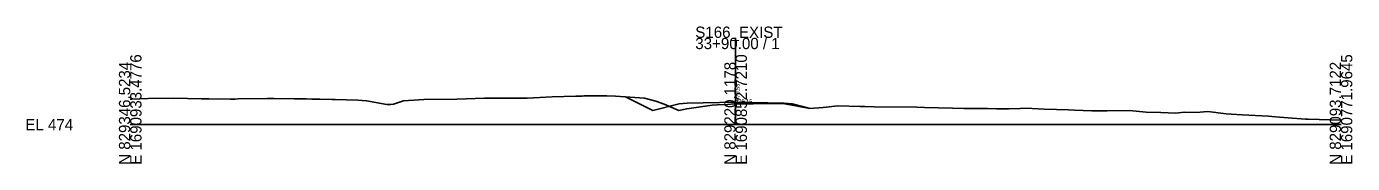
# Model space of a CAD drawing. Extents: x 1621104 to 1621433, y 1192880 to 1199414.
# Drawn here: x 1621104.2 to 1621432.7, y 1199379.5 to 1199413.7 of the extents above; entities that cross this region are included whole.
import ezdxf

# ---------------------------------------------------------------- set-up
doc = ezdxf.new("R2010")
doc.units = 0
for name, color, linetype in [('RD_GPK_XS_Cell', 7, 'Continuous'), ('RD_XS_EarthShd', 7, 'Continuous'), ('RD_XS_ExGround', 7, 'Continuous'), ('RD_XS_Pave', 7, 'Continuous'), ('RD_XS_TieSlope', 7, 'Continuous'), ('RD_XS_TX_Elev_EX', 7, 'Continuous'), ('RD_XS_TX_Elev_PR', 7, 'Continuous')]:
    doc.layers.add(name, color=color, linetype=linetype)

msp = doc.modelspace()

# ---------------------------------------------------------------- linework, layer by layer
at = {"layer": 'RD_GPK_XS_Cell'}
for p, q in [((1621279.86, 1199389.24), (1621279.86, 1199410.81)), ((1621129.86, 1199389.24), (1621279.86, 1199389.24)), ((1621279.86, 1199389.24), (1621429.86, 1199389.24))]:
    msp.add_line(p, q, dxfattribs=at)
at = {"layer": 'RD_XS_EarthShd'}
for p, q in [((1621267.86, 1199394.55), (1621265.86, 1199394.39)), ((1621291.86, 1199394.55), (1621293.86, 1199394.39))]:
    msp.add_line(p, q, dxfattribs=at)
at = {"layer": 'RD_XS_ExGround'}
msp.add_lwpolyline([(1621129.86, 1199395.56), (1621130.29, 1199395.6), (1621134.27, 1199395.7), (1621140.6, 1199395.83), (1621147.55, 1199395.66), (1621149.37, 1199395.64), (1621154.65, 1199395.53), (1621155.83, 1199395.6), (1621156.59, 1199395.64), (1621163.81, 1199395.69), (1621165.11, 1199395.71), (1621165.43, 1199395.7), (1621170.58, 1199395.64), (1621173.45, 1199395.61), (1621174.82, 1199395.55), (1621176.88, 1199395.56), (1621179.82, 1199395.48), (1621180.64, 1199395.45), (1621186.24, 1199395.33), (1621188.43, 1199395.16), (1621193.46, 1199394.21), (1621194.42, 1199394.22), (1621195.1, 1199394.36), (1621197.53, 1199395.13), (1621202.61, 1199395.48), (1621210.81, 1199395.59), (1621217.63, 1199395.79), (1621220.25, 1199395.83), (1621220.76, 1199395.84), (1621222.4, 1199395.83), (1621226.36, 1199395.84), (1621228.18, 1199395.84), (1621234.37, 1199396.16), (1621240.25, 1199396.27), (1621241.83, 1199396.35), (1621242.22, 1199396.36), (1621244.77, 1199396.38), (1621247.94, 1199396.43), (1621250.13, 1199396.34), (1621257.28, 1199395.85), (1621260.08, 1199395.07), (1621262.14, 1199394.29), (1621265.75, 1199392.77), (1621267.73, 1199393.19), (1621274.08, 1199394.1), (1621275.41, 1199394.15), (1621277.84, 1199394.27), (1621279.39, 1199394.39), (1621279.86, 1199394.39), (1621282.31, 1199394.41), (1621284.22, 1199394.37), (1621289.57, 1199394.46), (1621291.53, 1199394.46), (1621294.8, 1199393.92), (1621295.53, 1199393.72), (1621298.23, 1199393.26), (1621301.59, 1199393.47), (1621305.19, 1199393.87), (1621310.68, 1199393.72), (1621311.89, 1199393.7), (1621314.19, 1199393.65), (1621324.75, 1199393.54), (1621326.66, 1199393.52), (1621333.59, 1199393.32), (1621336.37, 1199393.25), (1621342.23, 1199393.26), (1621344.49, 1199393.15), (1621347.52, 1199393.16), (1621350.4, 1199393.28), (1621351.78, 1199393.36), (1621356.38, 1199393.1), (1621362.3, 1199392.89), (1621363.86, 1199392.82), (1621368.15, 1199392.7), (1621371.92, 1199392.67), (1621377.47, 1199392.76), (1621381.56, 1199392.35), (1621385.21, 1199392.26), (1621388.82, 1199392.12), (1621391.1, 1199392.34), (1621393.98, 1199392.23), (1621396.87, 1199392.48), (1621401.36, 1199391.94), (1621402.67, 1199391.82), (1621405.4, 1199391.67), (1621411.92, 1199391.33), (1621412.71, 1199391.24), (1621414.64, 1199391.11), (1621421.02, 1199390.61), (1621421.71, 1199390.55), (1621429.86, 1199390.3)], dxfattribs=at)
at = {"layer": 'RD_XS_Pave'}
for p, q in [((1621267.86, 1199394.55), (1621279.86, 1199394.79)), ((1621279.86, 1199394.79), (1621291.86, 1199394.55))]:
    msp.add_line(p, q, dxfattribs=at)
at = {"layer": 'RD_XS_TieSlope'}
for p, q in [((1621259.37, 1199392.77), (1621252.57, 1199396.17)), ((1621265.86, 1199394.39), (1621259.37, 1199392.77)), ((1621293.86, 1199394.39), (1621298.33, 1199393.27))]:
    msp.add_line(p, q, dxfattribs=at)

# ---------------------------------------------------------------- texts
at = {"layer": 'RD_GPK_XS_Cell'}
for s, p in [('S166_EXIST', (1621269.86, 1199410.81)), ('33+90.00 / 1', (1621269.86, 1199408.01)), ('EL 474', (1621103.86, 1199387.84))]:
    msp.add_text(s, height=2.8, dxfattribs=at).set_placement(p)
for s, p in [('N 829346.5234', (1621129.86, 1199379.24)), ('E 1690933.4776', (1621132.66, 1199379.24)), ('N 829220.1178', (1621279.86, 1199379.24)), ('E 1690852.7210', (1621282.66, 1199379.24)), ('N 829093.7122', (1621429.86, 1199379.24)), ('E 1690771.9645', (1621432.66, 1199379.24))]:
    msp.add_text(s, height=2.8, rotation=90, dxfattribs=at).set_placement(p)
at = {"layer": 'RD_XS_TX_Elev_EX'}
msp.add_text('479.15', height=1, dxfattribs=at).set_placement((1621279.76, 1199394.49))
at = {"layer": 'RD_XS_TX_Elev_PR'}
msp.add_text(' 479.55', height=1, rotation=90, dxfattribs=at).set_placement((1621280.86, 1199394.79))

doc.saveas('drawing.dxf')
